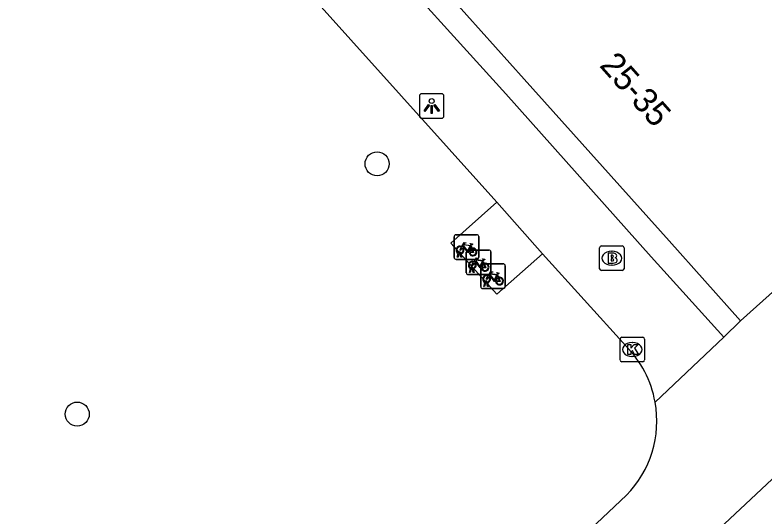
# Model space of a CAD drawing. Extents: x 162347 to 162868, y 381221 to 381813.
# Drawn here: x 162597.89 to 162628.37, y 381515.43 to 381535.82 of the extents above; entities that cross this region are included whole.
import ezdxf

# ---------------------------------------------------------------- set-up
doc = ezdxf.new("R2010")
doc.units = 0
for name, color, linetype in [('IMGEO_Boom', 7, 'Continuous'), ('IMGEO_Brandkraan', 7, 'Continuous'), ('IMGEO_Fietsenrek', 7, 'Continuous'), ('IMGEO_Kolk', 7, 'Continuous'), ('IMGEO_Lichtpunt', 7, 'Continuous'), ('IMGEO_Pand', 7, 'Continuous'), ('IMGEO_Pand_nummerreeks', 7, 'Continuous'), ('IMGEO_Rijbaan_lokaal_gesloten', 7, 'Continuous'), ('IMGEO_Voetpad_open', 7, 'Continuous')]:
    doc.layers.add(name, color=color, linetype=linetype)

msp = doc.modelspace()

# ---------------------------------------------------------------- linework, layer by layer
at = {"layer": 'IMGEO_Boom'}
for centre in [(162612.608, 381529.774), (162600.423, 381519.607)]:
    msp.add_circle(centre, 0.489, dxfattribs=at)
at = {"layer": 'IMGEO_Brandkraan'}
for p, q in [((162621.644, 381525.515), (162621.644, 381526.367)), ((162621.719, 381526.441), (162622.571, 381526.441)), ((162622.645, 381526.367), (162622.645, 381525.515)), ((162622.132, 381526.221), (162622.157, 381526.221)), ((162622.155, 381525.661), (162622.13, 381525.661)), ((162622.571, 381525.441), (162621.719, 381525.441))]:
    msp.add_line(p, q, dxfattribs=at)
for points in [[(162621.644, 381525.515), (162621.644, 381526.367)], [(162621.719, 381526.441), (162622.571, 381526.441)], [(162622.645, 381526.367), (162622.645, 381525.515)], [(162621.992, 381526.141), (162621.992, 381525.741), (162622.205, 381525.741)], [(162622.223, 381526.141), (162621.992, 381526.141)], [(162622.171, 381526.06), (162622.117, 381526.06), (162622.117, 381525.984)], [(162622.117, 381525.984), (162622.17, 381525.984)], [(162622.179, 381525.908), (162622.117, 381525.908), (162622.117, 381525.827)], [(162622.117, 381525.827), (162622.179, 381525.827)], [(162622.571, 381525.441), (162621.719, 381525.441)]]:
    msp.add_lwpolyline(points, dxfattribs=at)
for centre, radius, start, end in [((162621.721, 381526.365), 0.0765, 91.552, 178.448), ((162621.721, 381526.365), 0.0765, 91.552, 178.448), ((162622.569, 381526.365), 0.0765, 1.552, 88.448), ((162622.569, 381526.365), 0.0765, 1.552, 88.448), ((162622.172, 381526.022), 0.0379, 267.8285, 90.9355), ((162622.227, 381525.996), 0.145, 59.4692, 91.5367), ((162622.252, 381526.043), 0.0922, 285.5137, 58.1501), ((162622.18, 381525.867), 0.0404, 269.8759, 90.5077), ((162622.211, 381525.992), 0.251, 268.6676, 293.5347), ((162622.257, 381525.851), 0.105, 301.3115, 78.989), ((162621.721, 381525.517), 0.0765, 181.552, 268.448), ((162621.721, 381525.517), 0.0765, 181.552, 268.448), ((162622.569, 381525.517), 0.0765, 271.552, 358.448), ((162622.569, 381525.517), 0.0765, 271.552, 358.448)]:
    msp.add_arc(centre, radius, start, end, dxfattribs=at)
for centre, major_axis, ratio, start_param, end_param in [((162622.131, 381525.941), (-0.387, 0.002), 0.722429, 4.712389, 7.853982), ((162622.156, 381525.941), (-0.39, 0.002), 0.717154, 1.570796, 4.712389)]:
    msp.add_ellipse(centre, major_axis=major_axis, ratio=ratio, start_param=start_param, end_param=end_param, dxfattribs=at)
at = {"layer": 'IMGEO_Fietsenrek'}
for p, q in [((162615.736, 381525.967), (162615.736, 381526.808)), ((162615.736, 381526.808), (162615.736, 381525.967)), ((162615.811, 381526.892), (162616.652, 381526.892)), ((162616.652, 381526.892), (162615.811, 381526.892)), ((162616.736, 381526.817), (162616.736, 381525.976)), ((162616.736, 381525.976), (162616.736, 381526.817)), ((162616.423, 381526.441), (162616.459, 381526.346)), ((162615.863, 381525.976), (162615.902, 381526.136)), ((162615.932, 381526.124), (162615.897, 381525.976)), ((162615.974, 381526.148), (162615.973, 381526.152)), ((162616.015, 381525.976), (162615.981, 381526.118)), ((162616.005, 381526.159), (162616.006, 381526.152)), ((162616.013, 381526.122), (162616.048, 381525.976)), ((162616.233, 381525.347), (162616.233, 381526.188)), ((162616.233, 381526.188), (162616.233, 381525.347)), ((162616.308, 381526.272), (162617.149, 381526.272)), ((162617.149, 381526.272), (162616.308, 381526.272)), ((162617.233, 381526.197), (162617.233, 381525.356)), ((162617.233, 381525.356), (162617.233, 381526.197)), ((162616.661, 381525.892), (162615.82, 381525.892)), ((162615.82, 381525.892), (162616.661, 381525.892)), ((162615.897, 381525.976), (162615.863, 381525.976)), ((162616.048, 381525.976), (162616.015, 381525.976)), ((162616.92, 381525.821), (162616.956, 381525.726)), ((162616.36, 381525.356), (162616.399, 381525.516)), ((162616.429, 381525.504), (162616.394, 381525.356)), ((162616.471, 381525.528), (162616.47, 381525.532)), ((162616.512, 381525.356), (162616.478, 381525.498)), ((162616.502, 381525.539), (162616.503, 381525.532)), ((162616.51, 381525.502), (162616.545, 381525.356)), ((162616.816, 381524.786), (162616.816, 381525.627)), ((162616.816, 381525.627), (162616.816, 381524.786)), ((162616.891, 381525.711), (162617.732, 381525.711)), ((162617.732, 381525.711), (162616.891, 381525.711)), ((162617.816, 381525.636), (162617.816, 381524.795)), ((162617.816, 381524.795), (162617.816, 381525.636)), ((162617.158, 381525.272), (162616.317, 381525.272)), ((162616.317, 381525.272), (162617.158, 381525.272)), ((162616.394, 381525.356), (162616.36, 381525.356)), ((162616.545, 381525.356), (162616.512, 381525.356)), ((162617.503, 381525.26), (162617.539, 381525.165)), ((162616.943, 381524.795), (162616.982, 381524.955)), ((162617.012, 381524.943), (162616.977, 381524.795)), ((162617.054, 381524.967), (162617.053, 381524.971)), ((162617.095, 381524.795), (162617.061, 381524.937)), ((162617.085, 381524.978), (162617.086, 381524.971)), ((162617.093, 381524.941), (162617.128, 381524.795)), ((162617.741, 381524.711), (162616.9, 381524.711)), ((162616.9, 381524.711), (162617.741, 381524.711)), ((162616.977, 381524.795), (162616.943, 381524.795)), ((162617.128, 381524.795), (162617.095, 381524.795))]:
    msp.add_line(p, q, dxfattribs=at)
for points in [[(162616.07, 381526.366), (162616.018, 381526.276), (162615.978, 381526.251), (162615.979, 381526.298), (162616.034, 381526.392)], [(162616.049, 381526.418), (162616.144, 381526.582), (162616.23, 381526.568), (162616.232, 381526.559), (162616.176, 381526.548), (162616.149, 381526.503), (162616.405, 381526.462)], [(162616.345, 381526.174), (162616.295, 381526.174), (162616.104, 381526.425), (162616.085, 381526.393)], [(162616.392, 381526.437), (162616.135, 381526.478), (162616.118, 381526.449), (162616.285, 381526.229), (162616.392, 381526.437)], [(162616.44, 381526.339), (162616.41, 381526.416), (162616.301, 381526.198), (162616.344, 381526.198)], [(162616.405, 381526.462), (162616.43, 381526.511), (162616.424, 381526.515), (162616.401, 381526.519), (162616.389, 381526.526), (162616.388, 381526.529), (162616.39, 381526.534), (162616.485, 381526.519), (162616.487, 381526.509), (162616.477, 381526.496), (162616.465, 381526.49), (162616.451, 381526.496), (162616.423, 381526.441)], [(162616.374, 381526.198), (162616.494, 381526.197), (162616.45, 381526.311)], [(162616.47, 381526.318), (162616.525, 381526.173), (162616.375, 381526.173)], [(162616.567, 381525.746), (162616.515, 381525.656), (162616.475, 381525.631), (162616.476, 381525.678), (162616.531, 381525.772)], [(162616.546, 381525.798), (162616.641, 381525.962), (162616.727, 381525.948), (162616.729, 381525.939), (162616.673, 381525.928), (162616.646, 381525.883), (162616.902, 381525.842)], [(162616.842, 381525.554), (162616.792, 381525.554), (162616.601, 381525.805), (162616.582, 381525.773)], [(162616.889, 381525.817), (162616.632, 381525.858), (162616.615, 381525.829), (162616.782, 381525.609), (162616.889, 381525.817)], [(162616.937, 381525.719), (162616.907, 381525.796), (162616.798, 381525.578), (162616.841, 381525.578)], [(162616.902, 381525.842), (162616.927, 381525.891), (162616.921, 381525.895), (162616.898, 381525.899), (162616.886, 381525.906), (162616.885, 381525.909), (162616.887, 381525.914), (162616.982, 381525.899), (162616.984, 381525.889), (162616.974, 381525.876), (162616.962, 381525.87), (162616.948, 381525.876), (162616.92, 381525.821)], [(162616.871, 381525.578), (162616.991, 381525.577), (162616.947, 381525.691)], [(162616.967, 381525.698), (162617.022, 381525.553), (162616.872, 381525.553)], [(162617.15, 381525.185), (162617.098, 381525.095), (162617.058, 381525.07), (162617.059, 381525.117), (162617.114, 381525.211)], [(162617.129, 381525.237), (162617.224, 381525.401), (162617.31, 381525.387), (162617.312, 381525.378), (162617.256, 381525.367), (162617.229, 381525.322), (162617.485, 381525.281)], [(162617.425, 381524.993), (162617.375, 381524.993), (162617.184, 381525.244), (162617.165, 381525.212)], [(162617.472, 381525.256), (162617.215, 381525.297), (162617.198, 381525.268), (162617.365, 381525.048), (162617.472, 381525.256)], [(162617.52, 381525.158), (162617.49, 381525.235), (162617.381, 381525.017), (162617.424, 381525.017)], [(162617.485, 381525.281), (162617.51, 381525.33), (162617.504, 381525.334), (162617.481, 381525.338), (162617.469, 381525.345), (162617.468, 381525.348), (162617.47, 381525.353), (162617.565, 381525.338), (162617.567, 381525.328), (162617.557, 381525.315), (162617.545, 381525.309), (162617.531, 381525.315), (162617.503, 381525.26)], [(162617.454, 381525.017), (162617.574, 381525.016), (162617.53, 381525.13)], [(162617.55, 381525.137), (162617.605, 381524.992), (162617.455, 381524.992)]]:
    msp.add_lwpolyline(points, dxfattribs=at)
for centre, radius, start, end in [((162615.814, 381526.814), 0.0779, 92.4484, 184.2845), ((162615.814, 381526.814), 0.0779, 92.4484, 184.2845), ((162616.658, 381526.814), 0.0779, 2.4484, 94.2845), ((162616.658, 381526.814), 0.0779, 2.4484, 94.2845), ((162615.976, 381526.277), 0.159, 62.6766, 242.1369), ((162615.976, 381526.277), 0.129, 63.3192, 238.903), ((162615.976, 381526.277), 0.129, 283.6043, 43.4302), ((162615.976, 381526.277), 0.159, 283.5766, 46.6042), ((162615.956, 381526.148), 0.0499, 12.8025, 158.6934), ((162615.976, 381526.277), 0.159, 253.9967, 271.7867), ((162615.956, 381526.148), 0.0174, 12.8025, 163.4502), ((162615.976, 381526.277), 0.129, 253.415, 269.0204), ((162616.311, 381526.194), 0.0779, 92.4484, 184.2845), ((162616.311, 381526.194), 0.0779, 92.4484, 184.2845), ((162616.503, 381526.193), 0.159, 113.3408, 178.3217), ((162616.503, 381526.193), 0.159, 187.0065, 105.7708), ((162616.503, 381526.193), 0.129, 113.923, 177.9556), ((162616.503, 381526.193), 0.129, 188.6715, 104.5883), ((162617.155, 381526.194), 0.0779, 2.4484, 94.2845), ((162617.155, 381526.194), 0.0779, 2.4484, 94.2845), ((162615.814, 381525.97), 0.0779, 182.4484, 274.2845), ((162615.814, 381525.97), 0.0779, 182.4484, 274.2845), ((162616.473, 381525.657), 0.159, 62.6766, 242.1369), ((162616.473, 381525.657), 0.129, 63.3192, 238.903), ((162616.473, 381525.657), 0.159, 283.5766, 46.6042), ((162616.658, 381525.97), 0.0779, 272.4484, 4.2845), ((162616.658, 381525.97), 0.0779, 272.4484, 4.2845), ((162616.453, 381525.528), 0.0499, 12.8025, 158.6934), ((162616.473, 381525.657), 0.159, 253.9967, 271.7867), ((162616.453, 381525.528), 0.0174, 12.8025, 163.4502), ((162616.473, 381525.657), 0.129, 253.415, 269.0204), ((162616.473, 381525.657), 0.129, 283.6043, 43.4302), ((162616.894, 381525.633), 0.0779, 92.4484, 184.2845), ((162616.894, 381525.633), 0.0779, 92.4484, 184.2845), ((162617, 381525.573), 0.159, 113.3408, 178.3217), ((162617, 381525.573), 0.159, 187.0065, 105.7708), ((162617, 381525.573), 0.129, 113.923, 177.9556), ((162617, 381525.573), 0.129, 188.6715, 104.5883), ((162617.738, 381525.633), 0.0779, 2.4484, 94.2845), ((162617.738, 381525.633), 0.0779, 2.4484, 94.2845), ((162616.311, 381525.35), 0.0779, 182.4484, 274.2845), ((162616.311, 381525.35), 0.0779, 182.4484, 274.2845), ((162617.056, 381525.096), 0.159, 62.6766, 242.1369), ((162617.056, 381525.096), 0.129, 63.3192, 238.903), ((162617.056, 381525.096), 0.129, 283.6043, 43.4302), ((162617.056, 381525.096), 0.159, 283.5766, 46.6042), ((162617.155, 381525.35), 0.0779, 272.4484, 4.2845), ((162617.155, 381525.35), 0.0779, 272.4484, 4.2845), ((162617.583, 381525.012), 0.159, 113.3408, 178.3217), ((162617.583, 381525.012), 0.159, 187.0065, 105.7708), ((162617.036, 381524.967), 0.0499, 12.8025, 158.6934), ((162617.056, 381525.096), 0.159, 253.9967, 271.7867), ((162617.036, 381524.967), 0.0174, 12.8025, 163.4502), ((162617.056, 381525.096), 0.129, 253.415, 269.0204), ((162617.583, 381525.012), 0.129, 113.923, 177.9556), ((162617.583, 381525.012), 0.129, 188.6715, 104.5883), ((162616.894, 381524.789), 0.0779, 182.4484, 274.2845), ((162616.894, 381524.789), 0.0779, 182.4484, 274.2845), ((162617.738, 381524.789), 0.0779, 272.4484, 4.2845), ((162617.738, 381524.789), 0.0779, 272.4484, 4.2845)]:
    msp.add_arc(centre, radius, start, end, dxfattribs=at)
at = {"layer": 'IMGEO_Kolk'}
for p, q in [((162622.552, 381522.731), (162623.404, 381522.731)), ((162622.477, 381521.805), (162622.477, 381522.657)), ((162622.965, 381522.511), (162622.99, 381522.511)), ((162623.478, 381522.657), (162623.478, 381521.805)), ((162622.988, 381521.951), (162622.963, 381521.951)), ((162623.404, 381521.731), (162622.552, 381521.731))]:
    msp.add_line(p, q, dxfattribs=at)
for points in [[(162622.552, 381522.731), (162623.404, 381522.731)], [(162622.477, 381521.805), (162622.477, 381522.657)], [(162622.798, 381522.431), (162622.921, 381522.431), (162622.921, 381522.28), (162623.051, 381522.431), (162623.215, 381522.431), (162623.069, 381522.28), (162623.222, 381522.031), (162623.07, 381522.031), (162622.985, 381522.195), (162622.921, 381522.128), (162622.921, 381522.031), (162622.798, 381522.031), (162622.798, 381522.431)], [(162623.478, 381522.657), (162623.478, 381521.805)], [(162623.404, 381521.731), (162622.552, 381521.731)]]:
    msp.add_lwpolyline(points, dxfattribs=at)
for centre, start, end in [((162622.554, 381522.655), 91.552, 178.448), ((162622.554, 381522.655), 91.552, 178.448), ((162623.402, 381522.655), 1.552, 88.448), ((162623.402, 381522.655), 1.552, 88.448), ((162622.554, 381521.807), 181.552, 268.448), ((162622.554, 381521.807), 181.552, 268.448), ((162623.402, 381521.807), 271.552, 358.448), ((162623.402, 381521.807), 271.552, 358.448)]:
    msp.add_arc(centre, 0.0765, start, end, dxfattribs=at)
for centre, major_axis, ratio, start_param, end_param in [((162622.964, 381522.231), (-0.387, 0.002), 0.722429, 4.712389, 7.853982), ((162622.989, 381522.231), (-0.39, 0.002), 0.717154, 1.570796, 4.712389)]:
    msp.add_ellipse(centre, major_axis=major_axis, ratio=ratio, start_param=start_param, end_param=end_param, dxfattribs=at)
at = {"layer": 'IMGEO_Lichtpunt'}
for p, q in [((162614.327, 381532.526), (162614.327, 381531.719)), ((162614.327, 381532.526), (162614.327, 381531.719)), ((162615.229, 381532.621), (162614.421, 381532.621)), ((162615.229, 381532.621), (162614.421, 381532.621)), ((162615.323, 381531.719), (162615.323, 381532.526)), ((162615.323, 381531.719), (162615.323, 381532.526)), ((162614.421, 381531.625), (162615.229, 381531.625)), ((162614.421, 381531.625), (162615.229, 381531.625))]:
    msp.add_line(p, q, dxfattribs=at)
for points in [[(162614.701, 381532.19), (162614.74, 381532.162), (162614.552, 381531.9), (162614.514, 381531.927), (162614.701, 381532.19)], [(162614.913, 381532.162), (162614.951, 381532.189), (162615.138, 381531.927), (162615.099, 381531.899), (162614.913, 381532.162)], [(162614.803, 381532.142), (162614.85, 381532.142), (162614.85, 381531.82), (162614.803, 381531.82), (162614.803, 381532.142)]]:
    msp.add_lwpolyline(points, dxfattribs=at)
msp.add_circle((162614.826, 381532.324), 0.0994, dxfattribs=at)
for centre, start, end in [((162614.421, 381532.526), 90, 180), ((162614.421, 381532.526), 90, 180), ((162615.229, 381532.526), 0, 90), ((162615.229, 381532.526), 0, 90), ((162614.421, 381531.719), 180, 270), ((162614.421, 381531.719), 180, 270), ((162615.229, 381531.719), 270, 0), ((162615.229, 381531.719), 270, 360)]:
    msp.add_arc(centre, 0.0946, start, end, dxfattribs=at)
at = {"layer": 'IMGEO_Pand'}
for points in [[(162615.668, 381536.471), (162618.584, 381533.214), (162624.47, 381526.64), (162627.377, 381523.394)], [(162627.377, 381523.394), (162634.513, 381529.784)]]:
    msp.add_lwpolyline(points, dxfattribs=at)
at = {"layer": 'IMGEO_Rijbaan_lokaal_gesloten'}
msp.add_lwpolyline([(162626.296, 381514.744), (162630.602, 381518.772), (162630.767, 381518.982)], dxfattribs=at)
at = {"layer": 'IMGEO_Voetpad_open'}
for points in [[(162626.697, 381522.735), (162623.741, 381526.002), (162617.842, 381532.611), (162612.161, 381538.893), (162605.903, 381545.97), (162600.157, 381552.327), (162594.374, 381558.785), (162591.596, 381561.939)], [(162607.67, 381539.126), (162617.469, 381528.22)], [(162619.325, 381526.122), (162617.474, 381524.473), (162615.605, 381526.548), (162617.469, 381528.22)], [(162617.469, 381528.22), (162619.325, 381526.122)], [(162619.325, 381526.122), (162622.711, 381522.38)], [(162627.377, 381523.394), (162626.697, 381522.735)], [(162623.904, 381520.095), (162626.697, 381522.735)], [(162605.462, 381500), (162622.742, 381516.31)]]:
    msp.add_lwpolyline(points, dxfattribs=at)
for centre, start, end in [((162619.649, 381519.327), 10.2255, 44.9126), ((162619.648, 381519.331), 315.6893, 10.1776)]:
    msp.add_arc(centre, 4.324, start, end, dxfattribs=at)

# ---------------------------------------------------------------- texts
at = {"layer": 'IMGEO_Pand_nummerreeks'}
msp.add_text('25-35', height=1, rotation=311.6335, dxfattribs=at).set_placement((162621.61, 381533.753))

doc.saveas('drawing.dxf')
